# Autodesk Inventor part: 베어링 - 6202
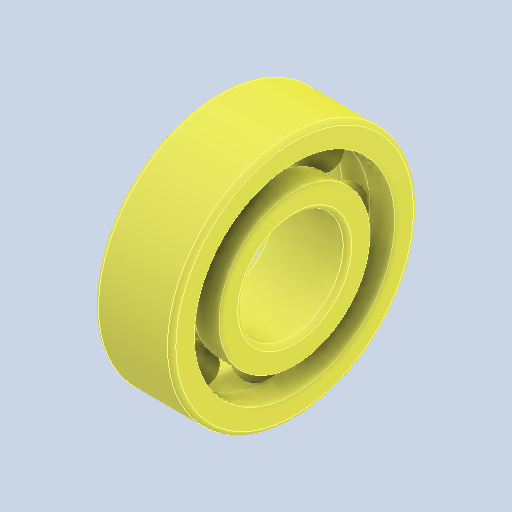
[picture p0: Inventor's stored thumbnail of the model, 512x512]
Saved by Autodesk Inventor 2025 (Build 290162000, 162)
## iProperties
Created: 2025-08
Part Number: 베어링 - 6202
Material: 강, 연강
Description: 깊은 그루브 볼 베어링
Document SubType Name: Modeling
Designer: infra017
Density: 7.86 g/cm^3
Appearance: 기본값
Author: jhkim
Sending System: Autodesk Inventor 2026
Preprocessor: ST-DEVELOPER v20.1
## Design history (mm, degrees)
feature "Solid1"
feature "Solid1:1"
feature "Solid1:2"
feature "Solid1:3"
feature "Solid1:4"
feature "Solid1:5"
feature "Solid1:6"
feature "Solid1:7"
feature "Solid1:8"
feature "Solid1:9"
node "솔리드1"
node "솔리드2"
node "솔리드3"
node "솔리드4"
node "솔리드5"
node "솔리드6"
node "솔리드7"
node "솔리드8"
node "솔리드9"
node "솔리드10"
